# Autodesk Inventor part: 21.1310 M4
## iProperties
Created: 2006-12
Part Number: 21.1310 M4
Document SubType Name: Modeling
Designer: Andy Moles
Material: Steel, Mild
Density: 7.86 g/cm^3
Author: Andy Moles
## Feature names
1. Extrusion1
2. Revolution1
